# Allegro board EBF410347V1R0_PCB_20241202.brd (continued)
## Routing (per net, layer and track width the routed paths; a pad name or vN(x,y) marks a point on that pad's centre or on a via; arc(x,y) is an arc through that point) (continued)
MIPI_CSI_RX0_D2P: length 71.2
  TOP w0.114: v1(38.16,50.39) 37.84,50.07 37.27,50.07 36.94,50.4 J3.120
  ART03 w0.102: v1(38.16,50.39) 38.42,50.14 39.03,50.14 39.45,49.72 39.45,45.98 39,45.54 37.63,45.54 36.63,44.54 31.85,44.54 30.95,45.44 19.27,45.44 19.11,45.29 17.82,45.29 17.66,45.44 5.99,45.44 4.95,44.4 4.95,41.04 5.28,40.71 5.28,37.49 4.52,36.73 4.52,30.06 3.87,29.41 2.13,29.41 1.75,29.79 1.75,30.6 2.09,30.94 2.42,30.94 v1(2.78,31.3)
  BOTTOM w0.114: v1(2.78,31.3) 3.16,30.92 3.63,30.92 4.39,31.68 4.39,34.35 5.16,35.12 5.62,35.12 5.75,35.25 J28.11
MIPI_CSI_RX0_D3N: length 76
  TOP w0.114: v1(39.5,51.3) 39.17,51.63 37.27,51.63 36.94,51.3 J3.119
  ART03 w0.102: v1(1.78,34.3) 2.14,34.66 2.62,34.66 2.97,35.01 2.97,44.59 5.32,46.94 14.97,46.94 15.74,47.7 19.93,47.7 20.16,47.93 29.4,47.93 29.68,48.22 29.68,48.58 29.8,48.7 29.97,48.7 30.09,48.58 30.09,48.22 30.36,47.95 30.79,47.95 31.06,48.22 31.06,48.58 31.18,48.7 31.47,48.7 31.6,48.56 31.6,47.17 31.88,46.89 32.28,46.89 32.56,47.17 32.56,48.65 32.68,48.77 32.85,48.77 32.97,48.65 32.97,47.17 33.25,46.89 33.65,46.89 33.94,47.17 33.94,48.65 34.05,48.77 34.22,48.77 34.34,48.65 34.34,47.17 34.62,46.89 36.31,46.89 36.91,47.48 36.91,48.01 36.62,48.3 35.55,48.3 35.43,48.42 35.43,48.58 35.55,48.7 36.62,48.7 36.91,48.99 36.91,51.28 37.21,51.59 39.21,51.59 v1(39.5,51.3)
  BOTTOM w0.114: v1(1.78,34.3) 2.18,34.7 2.55,34.7 2.91,35.05 2.91,36.6 3.19,36.88 5.62,36.88 5.75,36.75 J28.8
MIPI_CSI_RX0_D3P: length 76
  TOP w0.114: J3.118 36.94,52.2 37.27,51.87 39.17,51.87 v1(39.5,52.19)
  ART03 w0.102: v1(39.5,52.19) 39.17,51.87 37.1,51.87 36.63,51.4 36.63,49.1 36.51,48.98 35.44,48.98 35.15,48.7 35.15,48.3 35.44,48.02 36.51,48.02 36.63,47.9 36.63,47.6 36.2,47.17 34.74,47.17 34.62,47.29 34.62,48.76 34.34,49.05 33.94,49.05 33.66,48.76 33.66,47.29 33.54,47.17 33.37,47.17 33.25,47.29 33.25,48.76 32.97,49.05 32.57,49.05 32.28,48.76 32.28,47.29 32.17,47.17 32,47.17 31.88,47.29 31.88,48.68 31.58,48.98 31.06,48.98 30.78,48.69 30.78,48.34 30.68,48.23 30.47,48.23 30.37,48.34 30.37,48.69 30.09,48.98 29.69,48.98 29.41,48.69 29.41,48.33 29.28,48.21 20.04,48.21 19.81,47.98 15.62,47.98 14.86,47.22 5.21,47.22 2.69,44.7 2.69,35.13 2.5,34.94 2.14,34.94 v1(1.78,35.3)
  BOTTOM w0.114: v1(1.78,35.3) 2.14,34.94 2.45,34.94 2.67,35.15 2.67,36.7 3.09,37.12 5.62,37.12 5.75,37.25 J28.7
MIPI_CSI_RX1_CLK0N: length 62.7
  TOP w0.114: J3.116 36.94,54 37.27,54.33 37.84,54.33 v1(38.16,54)
  ART03 w0.102: v1(1.78,57.97) 2.14,58.33 2.43,58.33 2.59,58.16 2.59,57.41 1.63,56.45 1.63,56.05 arc(1.59,55.95) 1.49,55.92 arc(1.4,55.88) 1.36,55.78 1.36,55.64 arc(1.4,55.55) 1.49,55.51 arc(1.59,55.47) 1.63,55.38 1.63,55.23 arc(1.59,55.14) 1.49,55.1 arc(1.4,55.06) 1.36,54.97 1.36,54.83 arc(1.4,54.74) 1.49,54.7 arc(1.59,54.66) 1.63,54.56 1.63,50.15 1.99,49.78 4.63,49.78 4.93,49.48 34.41,49.48 35.33,50.4 35.33,53.88 35.76,54.31 37.86,54.31 v1(38.16,54)
  BOTTOM w0.114: J29.10 5.75,53.15 5.62,53.27 2.36,53.27 2,53.64 2,57.86 1.89,57.97 v1(1.78,57.97)
MIPI_CSI_RX1_CLK0P: length 62.7
  TOP w0.114: v1(38.16,54.89) 37.84,54.57 37.27,54.57 36.94,54.9 J3.115
  ART03 w0.102: v1(1.78,58.97) 2.14,58.61 2.54,58.61 2.87,58.28 2.87,57.3 1.91,56.33 1.91,50.27 2.11,50.06 4.74,50.06 5.04,49.76 34.3,49.76 35.05,50.52 35.05,54 35.64,54.59 37.86,54.59 v1(38.16,54.89)
  BOTTOM w0.114: J29.9 5.75,53.65 5.62,53.52 2.46,53.52 2.24,53.74 2.24,58.16 1.78,58.63 v1(1.78,58.97)
MIPI_CSI_RX1_CLK1N: length 64.6
  TOP w0.114: J3.108 36.94,61.2 37.27,61.53 39.2,61.53 v1(39.52,61.2)
  ART03 w0.102: v1(1.78,66.78) 2.14,67.14 2.6,67.14 2.89,67.42 2.89,68.14 3.01,68.26 3.18,68.26 3.29,68.14 3.29,67.42 3.58,67.14 3.98,67.14 4.26,67.42 4.26,68.14 4.38,68.26 4.55,68.26 4.67,68.14 4.67,67.42 4.95,67.14 5.35,67.14 5.63,67.42 5.63,68.14 5.75,68.26 5.92,68.26 6.04,68.14 6.04,67.42 6.32,67.14 8.44,67.14 8.68,66.91 8.68,59.61 9.06,59.23 33.49,59.23 33.83,59.58 33.83,61.01 34.31,61.48 39.24,61.48 v1(39.52,61.2)
  BOTTOM w0.114: v1(1.78,66.78) 2.17,67.17 2.61,67.17 2.98,67.54 2.98,70.46 3.17,70.64 5.62,70.64 5.75,70.51 J30.10
MIPI_CSI_RX1_CLK1P: length 64.6
  TOP w0.114: J3.107 36.94,62.1 37.27,61.77 39.2,61.77 v1(39.52,62.09)
  ART03 w0.102: v1(1.78,67.78) 2.14,67.42 2.49,67.42 2.61,67.54 2.61,68.26 2.89,68.54 3.29,68.54 3.57,68.26 3.57,67.54 3.69,67.42 3.86,67.42 3.98,67.54 3.98,68.26 4.26,68.54 4.66,68.54 4.95,68.26 4.95,67.54 5.06,67.42 5.23,67.42 5.35,67.54 5.35,68.26 5.63,68.54 6.03,68.54 6.32,68.26 6.32,67.54 6.44,67.42 8.56,67.42 8.96,67.02 8.96,59.73 9.17,59.51 33.37,59.51 33.55,59.69 33.55,61.13 34.19,61.76 39.19,61.76 v1(39.52,62.09)
  BOTTOM w0.114: v1(1.78,67.78) 2.15,67.41 2.51,67.41 2.74,67.64 2.74,70.56 3.07,70.88 5.62,70.88 5.75,71.01 J30.9
MIPI_CSI_RX1_D0N: length 66.2
  TOP w0.114: v1(38.8,56.7) 38.8,56.88 38.65,57.03 37.27,57.03 36.94,56.7 J3.113
  ART03 w0.102: v1(38.8,56.7) 38.8,56.88 38.67,57.01 37.21,57.01 36.72,56.52 34.74,56.52 34.63,56.4 34.63,54.13 34.26,53.76 33.72,53.76 33.35,54.13 33.35,56.31 33.15,56.52 30.55,56.52 30.31,56.27 30.31,55.97 30.43,55.85 31.95,55.85 32.23,55.56 32.23,55.16 31.95,54.88 30.43,54.88 30.31,54.76 30.31,54.59 30.43,54.48 31.95,54.48 32.23,54.19 32.23,53.79 31.95,53.51 30.43,53.51 30.31,53.39 30.31,53.02 30.43,52.9 30.95,52.9 31.23,52.62 31.23,52.22 30.95,51.94 30.43,51.94 30.31,51.82 30.31,51.56 arc(30.35,51.46) 30.45,51.42 arc(30.55,51.38) 30.59,51.27 30.59,51.15 arc(30.55,51.05) 30.45,51.01 arc(30.35,50.97) 30.31,50.87 30.31,50.56 29.94,50.2 6.91,50.2 6.64,50.46 6.64,51.25 6.54,51.35 6.26,51.35 6.15,51.24 6.15,50.45 5.88,50.18 5.29,50.18 5.02,50.45 5.02,51.33 4.82,51.54 4.17,51.54 4,51.37 4,50.75 4.11,50.65 v1(4.36,50.65)
  BOTTOM w0.114: v1(4.36,50.65) 4.1,50.65 3.99,50.76 3.99,52.04 4.22,52.27 5.62,52.27 5.75,52.15 J29.12
MIPI_CSI_RX1_D0P: length 66.2
  TOP w0.114: J3.112 36.94,57.6 37.27,57.27 38.47,57.27 v1(38.8,57.59)
  ART03 w0.102: v1(3.36,50.65) 3.72,51.01 3.72,51.49 4.05,51.81 4.94,51.81 5.3,51.45 5.3,50.57 5.41,50.46 5.77,50.46 5.87,50.57 5.87,51.36 6.14,51.63 6.66,51.63 6.92,51.37 6.92,50.58 7.03,50.48 29.82,50.48 30.03,50.68 30.03,51.93 30.31,52.22 30.83,52.22 30.95,52.33 30.95,52.5 30.83,52.62 30.31,52.62 30.03,52.9 30.03,53.51 30.31,53.79 31.83,53.79 31.95,53.91 31.95,54.08 31.83,54.2 30.31,54.2 30.03,54.48 30.03,54.88 30.31,55.16 31.83,55.16 31.95,55.28 31.95,55.45 31.83,55.57 30.31,55.57 30.03,55.85 30.03,56.39 30.44,56.8 33.26,56.8 33.63,56.43 33.63,54.25 33.84,54.04 34.14,54.04 34.35,54.24 34.35,56.52 34.62,56.8 36.6,56.8 37.1,57.29 38.49,57.29 v1(38.8,57.59)
  BOTTOM w0.114: v1(3.36,50.65) 3.75,51.03 3.75,52.14 4.12,52.52 5.62,52.52 5.75,52.65 J29.11
MIPI_CSI_RX1_D1N: length 63.7
  TOP w0.114: J3.111 36.94,58.5 37.27,58.83 39.17,58.83 v1(39.5,58.5)
  ART03 w0.102: v1(39.5,58.5) 39.19,58.81 36.55,58.81 36.35,58.61 36.35,57.67 36.02,57.34 29.75,57.34 29.56,57.15 29.56,55.6 29.28,55.32 28.54,55.32 28.42,55.2 28.42,55.03 28.54,54.92 29.28,54.92 29.56,54.63 29.56,54.23 29.28,53.95 28.54,53.95 28.42,53.83 28.42,53.66 28.54,53.54 29.28,53.54 29.56,53.26 29.56,51.4 29.06,50.9 19.26,50.9 18.68,51.48 16.1,51.48 15.52,50.9 7.8,50.9 7.4,51.3 7.4,52.14 7.25,52.3 6.81,52.3 6.54,52.58 6.54,53.36 6.43,53.47 6.26,53.47 6.14,53.35 6.14,52.59 5.85,52.29 5.45,52.29 5.17,52.57 5.17,53.52 5.07,53.62 4.91,53.62 4.79,53.5 4.79,52.61 4.48,52.29 3.98,52.29 3.71,52.56 3.71,55.3 v1(3.36,55.65)
  BOTTOM w0.114: v1(3.36,55.65) 3.73,55.28 3.73,54.62 4.08,54.27 5.62,54.27 5.75,54.15 J29.8
MIPI_CSI_RX1_D1P: length 63.6
  TOP w0.114: v1(39.5,59.39) 39.17,59.07 37.27,59.07 36.94,59.4 J3.110
  ART03 w0.102: v1(4.36,55.65) 3.99,55.27 3.99,52.68 4.09,52.57 4.36,52.57 4.51,52.73 4.51,53.62 4.8,53.9 5.19,53.9 5.45,53.64 5.45,52.68 5.56,52.57 5.73,52.57 5.86,52.7 5.86,53.47 6.14,53.75 6.54,53.75 6.82,53.48 6.82,52.69 6.93,52.58 7.36,52.58 7.68,52.26 7.68,51.41 7.91,51.18 15.4,51.18 15.99,51.76 18.8,51.76 19.38,51.18 28.94,51.18 29.28,51.52 29.28,53.15 29.16,53.26 28.43,53.26 28.14,53.55 28.14,53.95 28.43,54.23 29.16,54.23 29.28,54.35 29.28,54.52 29.16,54.64 28.43,54.64 28.14,54.92 28.14,55.32 28.43,55.6 29.16,55.6 29.28,55.72 29.28,57.26 29.64,57.62 33.1,57.62 arc(33.19,57.66) 33.23,57.74 arc(33.26,57.83) 33.35,57.87 33.51,57.87 arc(33.6,57.83) 33.63,57.74 arc(33.67,57.66) 33.75,57.62 33.92,57.62 arc(34,57.66) 34.04,57.74 arc(34.07,57.83) 34.16,57.87 34.32,57.87 arc(34.41,57.83) 34.45,57.74 arc(34.48,57.66) 34.57,57.62 34.73,57.62 arc(34.82,57.66) 34.85,57.74 arc(34.89,57.83) 34.97,57.87 35.14,57.87 arc(35.22,57.83) 35.26,57.74 arc(35.29,57.66) 35.38,57.62 35.91,57.62 36.07,57.78 36.07,58.72 36.43,59.09 39.19,59.09 v1(39.5,59.39)
  BOTTOM w0.114: v1(4.36,55.65) 3.98,55.26 3.98,54.72 4.18,54.52 5.62,54.52 5.75,54.65 J29.7
MIPI_CSI_RX1_D2N: length 68.2
  TOP w0.114: v1(40.79,62.09) 41.17,61.72 41.61,61.72 41.81,61.92 41.81,62.64 41.62,62.83 38.84,62.83 38.52,63.15 38.52,63.91 38.2,64.23 37.27,64.23 36.94,63.9 J3.105
  ART03 w0.102: v1(1.78,64.78) 2.09,65.09 7.41,65.09 7.81,64.69 7.81,59.03 8.32,58.52 33.96,58.52 34.57,59.13 34.57,59.89 34.85,60.17 41.64,60.17 41.96,60.49 41.96,61.41 41.59,61.79 41.1,61.79 v1(40.79,62.09)
  BOTTOM w0.114: v1(1.78,64.78) 2.14,65.14 3.53,65.14 3.91,65.52 3.91,69.5 4.06,69.64 5.62,69.64 5.75,69.51 J30.12
MIPI_CSI_RX1_D2P: length 68.1
  TOP w0.114: v1(40.79,61.2) 41.07,61.48 41.71,61.48 42.05,61.82 42.05,62.74 41.72,63.07 38.94,63.07 38.76,63.24 38.76,64.01 38.3,64.47 37.27,64.47 36.94,64.8 J3.104
  ART03 w0.102: v1(40.79,61.2) 41.1,61.51 41.47,61.51 41.68,61.3 41.68,60.6 41.53,60.45 34.73,60.45 34.29,60.01 34.29,59.24 33.85,58.8 8.43,58.8 8.09,59.15 8.09,64.8 7.52,65.37 2.19,65.37 v1(1.78,65.78)
  BOTTOM w0.114: v1(1.78,65.78) 2.18,65.38 3.43,65.38 3.67,65.62 3.67,69.59 3.96,69.88 5.62,69.88 5.75,70.01 J30.11
MIPI_CSI_RX1_D3N: length 68.7
  TOP w0.114: v1(39.69,63.83) 40.08,64.22 40.08,65.89 39.94,66.03 37.27,66.03 36.94,65.7 J3.103
  ART03 w0.102: v1(39.69,63.83) 40.03,64.17 40.03,64.45 39.8,64.68 39.17,64.68 38.96,64.48 38.96,62.65 38.6,62.28 38.09,62.28 37.8,62.56 37.8,63.48 37.68,63.6 37.52,63.6 37.4,63.48 37.4,62.56 37.11,62.28 34.08,62.28 31.76,59.96 9.92,59.96 9.48,60.4 9.48,69.22 9.28,69.43 9.05,69.43 arc(8.94,69.38) 8.9,69.28 arc(8.86,69.18) 8.75,69.13 8.64,69.13 arc(8.54,69.18) 8.49,69.28 arc(8.45,69.38) 8.35,69.43 8.24,69.43 arc(8.13,69.38) 8.09,69.28 arc(8.05,69.18) 7.94,69.13 7.83,69.13 arc(7.73,69.18) 7.68,69.28 arc(7.64,69.38) 7.53,69.43 7.42,69.43 arc(7.32,69.38) 7.28,69.28 arc(7.23,69.18) 7.13,69.13 7.02,69.13 arc(6.91,69.18) 6.87,69.28 arc(6.83,69.38) 6.72,69.43 6.61,69.43 arc(6.51,69.38) 6.46,69.28 arc(6.42,69.18) 6.32,69.13 6.2,69.13 arc(6.1,69.18) 6.06,69.28 arc(6.01,69.38) 5.91,69.43 5.8,69.43 arc(5.69,69.38) 5.65,69.28 arc(5.61,69.18) 5.5,69.13 5.39,69.13 arc(5.29,69.18) 5.24,69.28 arc(5.2,69.38) 5.1,69.43 4.98,69.43 arc(4.88,69.38) 4.84,69.28 arc(4.79,69.18) 4.69,69.13 4.58,69.13 arc(4.47,69.18) 4.43,69.28 arc(4.39,69.38) 4.28,69.43 3.99,69.43 3.61,69.81 3.61,71.88 3.4,72.08 2.67,72.08 2.42,71.84 2.42,71.38 2.52,71.27 v1(2.78,71.27)
  BOTTOM w0.114: J30.8 5.75,71.51 5.6,71.67 2.92,71.67 2.78,71.53 v1(2.78,71.27)
MIPI_CSI_RX1_D3P: length 68.8
  TOP w0.114: J3.102 36.94,66.6 37.27,66.27 40.04,66.27 40.32,65.99 40.32,64.2 v1(40.69,63.83)
  ART03 w0.102: v1(1.78,71.27) 2.14,71.63 2.14,71.95 2.55,72.36 3.52,72.36 3.89,72 3.89,69.93 4.11,69.71 9.39,69.71 9.76,69.34 9.76,60.51 10.04,60.24 31.64,60.24 33.97,62.56 37,62.56 37.12,62.68 37.12,63.6 37.4,63.88 37.8,63.88 38.08,63.6 38.08,62.68 38.2,62.56 38.48,62.56 38.68,62.76 38.68,64.59 39.06,64.96 39.92,64.96 40.31,64.57 40.31,64.21 v1(40.69,63.83)
  BOTTOM w0.114: J30.7 5.75,72.01 5.64,71.91 2.74,71.91 2.11,71.27 v1(1.78,71.27)
MIPI_CTP_INT: length 21.6
  BOTTOM w0.173: J18.11 61.18,15.54 61.49,15.86 63.26,15.86 64.25,16.85 77.93,16.85 R176.2 R81.2
MIPI_CTP_RST: length 17.7
  BOTTOM w0.173: J18.12 60.68,15.84 61.02,16.18 63.13,16.18 64.12,17.17 73.68,17.17 R177.2 R182.2
MIPI_DSI_CLKN: length 70.2
  TOP w0.114: R106.2 v1(24.7,35.43)
  ART03 w0.102: v1(24.7,35.43) 25.06,35.79 25.06,36.05 25.37,36.36 30.18,36.36 31.37,35.17 31.37,28.98 31.65,28.7 36.87,28.7 37.13,28.44 40.54,28.44 41.57,27.41 45.25,27.41 45.75,26.91 45.75,24.97 46.18,24.54 50.71,24.54 51.18,24.07 51.18,17.02 51.38,16.81 57.86,16.81 58.17,16.51 58.17,15.1 58.41,14.86 60.6,14.86 60.92,14.55 60.92,11.97 v1(61.22,11.66)
  BOTTOM w0.114: J18.24 54.68,13.7 54.8,13.58 54.8,10.9 55.25,10.45 60.5,10.45 60.87,10.82 60.87,11.31 v1(61.22,11.66)
MIPI_DSI_CLKP: length 69.7
  TOP w0.114: R105.2 v1(25.7,35.43)
  ART03 w0.102: v1(60.33,11.66) 60.53,11.66 60.64,11.77 60.64,14.43 60.49,14.58 58.29,14.58 57.89,14.98 57.89,16.39 57.75,16.53 51.27,16.53 50.9,16.9 50.9,23.95 50.6,24.26 46.06,24.26 45.47,24.85 45.47,26.8 45.14,27.13 41.45,27.13 40.42,28.16 37.02,28.16 36.75,28.42 31.53,28.42 31.09,28.86 31.09,29.36 30.91,29.54 30.91,29.77 31.09,29.95 31.09,30.17 30.91,30.35 30.91,30.58 31.09,30.76 31.09,30.99 30.91,31.16 30.91,31.39 31.09,31.57 31.09,31.8 30.91,31.98 30.91,32.21 31.09,32.38 31.09,32.61 30.91,32.79 30.91,33.02 31.09,33.2 31.09,33.43 30.91,33.6 30.91,33.83 31.09,34.01 31.09,34.24 30.91,34.42 30.91,34.64 31.09,34.82 31.09,35.05 30.06,36.08 25.48,36.08 25.34,35.94 25.34,35.53 25.44,35.43 v1(25.7,35.43)
  BOTTOM w0.114: v1(60.33,11.66) 60.63,11.36 60.63,10.92 60.4,10.69 55.35,10.69 55.04,11 55.04,13.56 55.18,13.7 J18.23
MIPI_DSI_D0N: length 72.3
  TOP w0.114: R88.2 v1(28.7,35.43)
  ART03 w0.102: v1(28.7,35.43) 29.06,35.07 29.06,33.32 29.76,32.62 29.76,32.39 29.64,32.27 28.63,32.27 28.35,31.99 28.35,31.59 28.63,31.31 29.64,31.31 29.76,31.19 29.76,29.75 29.64,29.63 28.6,29.63 28.32,29.35 28.32,28.95 28.6,28.67 29.64,28.67 29.76,28.55 29.76,27.86 30.21,27.41 36.19,27.41 36.7,26.9 39.38,26.9 39.89,26.39 44.02,26.39 44.25,26.16 44.25,23.05 44.77,22.53 49.96,22.53 50.16,22.33 50.16,16.1 50.72,15.54 56.79,15.54 57.07,15.26 57.07,14.25 57.58,13.74 59.16,13.74 59.41,13.49 59.41,10.41 59.03,10.03 54.51,10.03 54.25,10.29 54.25,11.57 53.84,11.99 53.07,11.99 52.79,11.7 52.79,10.8 v1(52.48,10.49)
  BOTTOM w0.114: v1(52.48,10.49) 52.81,10.81 52.81,11.73 53.3,12.23 53.3,13.58 53.18,13.7 J18.27
MIPI_DSI_D0P: length 73.3
  TOP w0.114: R87.2 v1(29.7,35.43)
  ART03 w0.102: v1(53.37,10.49) 53.07,10.8 53.07,11.59 53.19,11.71 53.72,11.71 53.98,11.45 53.98,10.17 54.39,9.75 59.15,9.75 59.69,10.3 59.69,13.6 59.27,14.02 57.7,14.02 57.35,14.36 57.35,15.38 56.91,15.82 50.84,15.82 50.44,16.22 50.44,22.44 50.08,22.81 44.88,22.81 44.53,23.16 44.53,26.28 44.13,26.67 40.01,26.67 39.5,27.18 38.54,27.18 38.36,27.35 38.13,27.35 37.95,27.18 37.72,27.18 37.55,27.35 37.32,27.35 37.14,27.18 36.82,27.18 36.31,27.68 35.58,27.68 35.43,27.84 35.12,27.84 34.97,27.68 33.9,27.68 33.72,27.86 33.47,27.86 33.29,27.68 32.47,27.68 32.29,27.86 32.07,27.86 31.89,27.68 31.66,27.68 31.48,27.86 31.25,27.86 31.08,27.68 30.33,27.68 30.04,27.97 30.04,28.67 29.76,28.95 28.72,28.95 28.6,29.07 28.6,29.24 28.72,29.35 29.76,29.35 30.04,29.64 30.04,31.31 29.76,31.59 28.74,31.59 28.63,31.71 28.63,31.88 28.74,31.99 29.76,31.99 30.04,32.28 30.04,32.74 29.34,33.44 29.34,35.07 v1(29.7,35.43)
  BOTTOM w0.114: v1(53.37,10.49) 53.21,10.49 53.05,10.65 53.05,11.63 53.54,12.13 53.54,13.56 53.68,13.7 J18.26
MIPI_DSI_D1N: length 70.5
  TOP w0.114: R92.2 v1(26.7,35.43)
  ART03 w0.102: v1(26.7,35.43) 27.06,35.07 27.06,33.46 26.94,33.34 24.95,33.34 24.66,33.06 24.66,32.66 24.97,32.35 27.4,32.35 27.52,32.23 27.52,32.06 27.4,31.94 24.92,31.94 24.66,31.69 24.66,31.29 24.97,30.98 27.4,30.98 27.52,30.86 27.52,30.69 27.4,30.57 24.93,30.57 24.66,30.31 24.66,29.75 24.95,29.46 27.41,29.46 27.51,29.36 27.51,27.83 27.79,27.55 28.79,27.55 28.91,27.43 28.91,27.26 28.79,27.14 27.79,27.14 27.51,26.86 27.51,26.35 27.9,25.96 30.71,25.96 31.27,25.4 36.62,25.4 36.78,25.56 42.54,25.56 43.51,24.6 43.51,22.01 43.98,21.54 49.11,21.54 49.4,21.24 49.4,15.11 49.89,14.63 55.85,14.63 56.29,14.19 56.29,12.8 v1(55.99,12.5)
  BOTTOM w0.114: J18.21 56.18,13.7 56.31,13.57 56.31,12.82 v1(55.99,12.5)
MIPI_DSI_D1P: length 70.8
  TOP w0.114: R91.2 v1(27.7,35.43)
  ART03 w0.102: v1(27.7,35.43) 27.34,35.07 27.34,33.34 27.06,33.06 25.06,33.06 24.94,32.94 24.94,32.77 25.09,32.63 27.52,32.63 27.8,32.35 27.8,31.95 27.52,31.66 25.04,31.66 24.94,31.56 24.94,31.4 25.09,31.26 27.52,31.26 27.8,30.97 27.8,30.57 27.52,30.29 25.04,30.29 24.94,30.19 24.94,29.87 25.07,29.74 27.52,29.74 27.79,29.48 27.79,27.95 27.91,27.83 28.9,27.83 29.18,27.55 29.18,27.15 28.9,26.86 27.91,26.86 27.79,26.75 27.79,26.47 28.02,26.24 28.92,26.24 29.1,26.41 29.33,26.41 29.51,26.24 29.74,26.24 29.91,26.41 30.14,26.41 30.32,26.24 30.82,26.24 31.38,25.68 36.5,25.68 36.66,25.84 42.66,25.84 43.79,24.71 43.79,22.12 44.09,21.82 49.23,21.82 49.68,21.36 49.68,15.23 50,14.91 55.97,14.91 56.57,14.31 56.57,12.8 v1(56.88,12.5)
  BOTTOM w0.114: J18.20 56.68,13.7 56.55,13.57 56.55,12.82 v1(56.88,12.5)
MIPI_DSI_D2N: length 70.4
  TOP w0.114: R96.2 v1(22.7,35.43)
  ART03 w0.102: v1(58.7,11.45) 58.4,11.75 58.02,11.75 57.89,11.62 57.89,10.93 57.55,10.59 55.26,10.59 54.89,10.96 54.89,13.51 54.64,13.77 49.11,13.77 48.64,14.23 48.64,20.45 48.46,20.62 42.61,20.62 42.19,21.04 42.19,23.66 41.28,24.56 37,24.56 36.79,24.36 30.86,24.36 30.44,24.78 27.23,24.78 26.52,25.49 26.52,28.26 26.3,28.47 23.94,28.47 23.67,28.74 23.67,29.24 23.55,29.36 22.41,29.36 22.12,29.64 22.12,30.04 22.41,30.32 23.55,30.32 23.67,30.44 23.67,30.73 23.44,30.96 22.35,30.96 22.08,31.23 22.08,31.6 22.35,31.87 23.55,31.87 23.65,31.97 23.65,32.13 23.5,32.28 22.41,32.28 22.07,32.62 22.07,33.02 22.35,33.3 22.94,33.3 23.06,33.42 23.06,35.07 v1(22.7,35.43)
  BOTTOM w0.114: J18.18 57.68,13.7 57.81,13.57 57.81,12.08 58.12,11.77 58.38,11.77 v1(58.7,11.45)
MIPI_DSI_D2P: length 70.9
  TOP w0.114: R95.2 v1(23.7,35.43)
  ART03 w0.102: v1(58.7,12.34) 58.4,12.03 57.91,12.03 57.61,11.73 57.61,11.05 57.43,10.87 55.37,10.87 55.17,11.07 55.17,13.63 54.75,14.05 49.23,14.05 48.92,14.35 48.92,20.56 48.58,20.9 42.72,20.9 42.47,21.16 42.47,23.77 41.4,24.84 36.88,24.84 36.68,24.64 35.96,24.64 35.78,24.81 35.55,24.81 35.38,24.64 35.15,24.64 34.97,24.81 34.74,24.81 34.56,24.64 33.66,24.64 33.48,24.81 33.25,24.81 33.07,24.64 31.92,24.64 31.74,24.81 31.48,24.81 31.31,24.64 30.98,24.64 30.56,25.06 29.11,25.06 28.94,25.22 28.7,25.22 28.53,25.06 28.29,25.06 28.13,25.22 27.89,25.22 27.72,25.06 27.34,25.06 26.8,25.6 26.8,26.49 26.97,26.67 26.97,26.9 26.8,27.07 26.8,27.3 26.97,27.48 26.97,27.71 26.8,27.89 26.8,28.37 26.42,28.75 24.05,28.75 23.95,28.85 23.95,29.35 23.67,29.64 22.52,29.64 22.4,29.76 22.4,29.92 22.52,30.04 23.67,30.04 23.95,30.33 23.95,30.85 23.56,31.24 22.47,31.24 22.36,31.34 22.36,31.49 22.47,31.59 23.66,31.59 23.93,31.85 23.93,32.25 23.62,32.55 22.53,32.55 22.35,32.73 22.35,32.9 22.47,33.02 23.06,33.02 23.34,33.3 23.34,35.3 23.47,35.43 v1(23.7,35.43)
  BOTTOM w0.114: J18.17 58.18,13.7 58.05,13.57 58.05,12.18 58.22,12.01 58.38,12.01 v1(58.7,12.34)
MIPI_DSI_D3N: length 71.5
  TOP w0.114: R101.2 20.7,35.43 v1(20.7,35.43)
  ART03 w0.102: v1(20.7,35.43) 20.96,35.43 21.06,35.33 21.06,28.06 21.34,27.77 22.23,27.77 22.35,27.65 22.35,27.49 22.23,27.37 21.34,27.37 21.06,27.08 21.06,26.68 21.34,26.4 22.23,26.4 22.35,26.28 22.35,26.11 22.23,25.99 21.34,25.99 21.06,25.71 21.06,25.31 21.34,25.03 22.23,25.03 22.35,24.91 22.35,24.74 22.23,24.62 21.34,24.62 21.06,24.34 21.06,23.68 21.47,23.27 22.97,23.27 23.25,23.55 23.25,24.06 23.37,24.18 23.54,24.18 23.66,24.06 23.66,23.55 23.94,23.27 24.34,23.27 24.63,23.55 24.63,24.06 24.74,24.18 24.91,24.18 25.03,24.06 25.03,23.55 25.31,23.27 25.71,23.27 26,23.55 26,24.06 26.12,24.18 26.28,24.18 26.4,24.06 26.4,23.55 26.69,23.27 27.23,23.27 27.51,23.55 27.51,23.96 27.63,24.07 27.8,24.07 27.91,23.96 27.91,23.55 28.2,23.27 28.6,23.27 28.88,23.55 28.88,23.96 28.99,24.07 29.13,24.07 29.24,23.97 29.24,23.56 29.53,23.27 41.22,23.27 41.48,23.01 41.48,19.16 41.9,18.74 47.68,18.74 47.88,18.54 47.88,13.28 48.3,12.86 51.73,12.86 51.97,12.62 51.97,12.07 51.81,11.91 51.18,11.91 51.08,12.01 v1(51.08,12.21)
  BOTTOM w0.114: v1(51.08,12.21) 51.08,12.04 51.23,11.89 51.61,11.89 51.8,12.08 51.8,13.57 51.68,13.7 J18.30
MIPI_DSI_D3P: length 72
  TOP w0.114: R100.2 v1(21.7,35.43)
  ART03 w0.102: v1(51.08,11.32) 51.38,11.63 51.93,11.63 52.25,11.95 52.25,12.73 51.85,13.14 48.41,13.14 48.16,13.39 48.16,18.66 47.79,19.02 42.01,19.02 41.76,19.28 41.76,23.13 41.34,23.54 29.64,23.54 29.51,23.67 29.51,24.08 29.25,24.35 28.87,24.35 28.6,24.07 28.6,23.66 28.48,23.54 28.31,23.54 28.19,23.66 28.19,24.07 27.91,24.35 27.51,24.35 27.23,24.07 27.23,23.66 27.11,23.54 26.8,23.54 26.68,23.66 26.68,24.18 26.4,24.46 26,24.46 25.72,24.18 25.72,23.66 25.6,23.54 25.43,23.54 25.31,23.66 25.31,24.18 25.03,24.46 24.63,24.46 24.35,24.18 24.35,23.66 24.23,23.54 24.06,23.54 23.94,23.66 23.94,24.18 23.66,24.46 23.26,24.46 22.97,24.18 22.97,23.66 22.86,23.54 21.59,23.54 21.34,23.79 21.34,24.22 21.46,24.34 22.35,24.34 22.63,24.63 22.63,25.03 22.35,25.31 21.46,25.31 21.34,25.43 21.34,25.6 21.46,25.72 22.35,25.72 22.63,26 22.63,26.4 22.35,26.68 21.46,26.68 21.34,26.8 21.34,26.97 21.46,27.09 22.35,27.09 22.63,27.37 22.63,27.77 22.35,28.05 21.46,28.05 21.34,28.17 21.34,35.07 v1(21.7,35.43)
  BOTTOM w0.114: v1(51.08,11.32) 51.4,11.64 51.71,11.64 52.04,11.98 52.04,13.57 52.18,13.7 J18.29
MIPI_DSI_TX_CLKN: length 25.2
  TOP w0.114: J3.135 36.94,36.9 37.27,37.23 39.14,37.23 39.38,36.98 39.38,36.59 39.27,36.47 v1(39.06,36.47) ; R107.1 v1(24.7,33.72) R106.1
  BOTTOM w0.114: v1(39.06,36.47) 39.38,36.15 39.38,35.99 39.24,35.84 38.85,35.84 38.44,36.24 38.44,36.69 37.68,37.45 33.78,37.45 32.96,36.62 32.96,34.43 32.69,34.17 30.73,34.17 30.21,34.68 25.4,34.68 25.08,34.36 25.08,34.1 v1(24.7,33.72)
MIPI_DSI_TX_CLKP: length 25.6
  TOP w0.114: R105.1 v1(25.7,33.72) R104.1 ; v1(39.95,36.47) 39.74,36.47 39.62,36.59 39.62,37.08 39.24,37.47 37.27,37.47 36.94,37.8 J3.134
  BOTTOM w0.114: v1(39.95,36.47) 39.62,36.15 39.62,35.89 39.34,35.6 38.75,35.6 38.2,36.14 38.2,36.59 37.58,37.21 33.88,37.21 33.2,36.52 33.2,34.33 32.79,33.92 30.63,33.92 30.11,34.44 25.5,34.44 25.32,34.26 25.32,34.1 v1(25.7,33.72)
MIPI_DSI_TX_D0N: length 23.1
  TOP w0.114: R89.1 v1(28.7,33.72) R88.1 ; J3.138 36.94,34.2 37.27,34.53 39.17,34.53 v1(39.5,34.2)
  BOTTOM w0.114: v1(28.7,33.72) 28.99,33.72 29.48,33.22 33.67,33.22 33.92,33.48 33.92,36.21 34.18,36.46 35.86,36.46 35.98,36.35 35.98,35.05 36.23,34.8 36.78,34.8 37.03,35.05 37.03,36.18 37.15,36.3 37.31,36.3 37.45,36.16 37.45,34.98 37.91,34.53 39.17,34.53 v1(39.5,34.2)
MIPI_DSI_TX_D0P: length 22.1
  TOP w0.114: v1(39.5,35.09) 39.17,34.77 37.27,34.77 36.94,35.1 J3.137 ; R87.1 v1(29.7,33.72) R86.1
  BOTTOM w0.114: v1(39.5,35.09) 39.17,34.77 38.01,34.77 37.69,35.08 37.69,36.26 37.41,36.54 37.05,36.54 36.79,36.28 36.79,35.15 36.68,35.04 36.33,35.04 36.22,35.15 36.22,36.45 35.96,36.7 34.08,36.7 33.68,36.31 33.68,33.58 33.57,33.47 29.82,33.47 29.7,33.58 v1(29.7,33.72)
MIPI_DSI_TX_D1N: length 24.9
  TOP w0.114: R93.1 v1(26.7,33.72) R92.1 ; J3.140 36.94,32.4 37.27,32.73 37.84,32.73 v1(38.16,32.4)
  BOTTOM w0.114: v1(26.7,33.72) 27.08,33.34 27.08,32.77 27.34,32.51 34.38,32.51 34.63,32.77 34.63,35.58 34.77,35.72 35.15,35.72 35.27,35.61 35.27,32.33 35.68,31.93 36.2,31.93 36.53,32.26 36.53,33.71 36.64,33.82 37.01,33.82 37.12,33.71 37.12,33.02 37.42,32.73 37.84,32.73 v1(38.16,32.4)
MIPI_DSI_TX_D1P: length 24.5
  TOP w0.114: R91.1 v1(27.7,33.72) R90.1 ; v1(38.16,33.29) 37.84,32.97 37.27,32.97 36.94,33.3 J3.139
  BOTTOM w0.114: v1(38.16,33.29) 37.84,32.97 37.52,32.97 37.36,33.12 37.36,33.81 37.11,34.06 36.54,34.06 36.29,33.81 36.29,32.36 36.1,32.17 35.78,32.17 35.51,32.43 35.51,35.71 35.25,35.97 34.67,35.97 34.39,35.68 34.39,32.87 34.28,32.75 27.44,32.75 27.32,32.87 27.32,33.34 v1(27.7,33.72)
MIPI_DSI_TX_D2N: length 24.9
  TOP w0.114: R97.1 v1(22.7,33.72) R96.1 ; v1(39.5,30.6) 39.17,30.93 37.27,30.93 36.94,30.6 J3.142
  BOTTOM w0.114: v1(39.5,30.6) 39.17,30.93 34.64,30.93 33.78,31.79 24.98,31.79 24.71,32.06 24.71,32.47 24.57,32.6 24.38,32.6 24.25,32.47 24.25,32.06 23.97,31.79 23.34,31.79 23.08,32.04 23.08,33.34 v1(22.7,33.72)
MIPI_DSI_TX_D2P: length 24.5
  TOP w0.114: R94.1 v1(23.7,33.72) R95.1 ; v1(39.5,31.49) 39.17,31.17 37.27,31.17 36.94,31.5 J3.141
  BOTTOM w0.114: v1(23.7,33.72) 23.32,33.34 23.32,32.14 23.44,32.03 23.87,32.03 24.01,32.16 24.01,32.57 24.28,32.84 24.67,32.84 24.95,32.57 24.95,32.16 25.08,32.03 33.88,32.03 34.74,31.17 39.17,31.17 v1(39.5,31.49)
MIPI_DSI_TX_D3N: length 23.8
  TOP w0.114: J3.144 36.94,28.8 37.27,29.13 37.84,29.13 v1(38.16,28.8) ; R101.1 20.7,33.72 v1(20.7,33.72) R102.1
  BOTTOM w0.114: v1(20.7,33.72) 21.08,33.34 21.08,32.02 22.04,31.06 33.45,31.06 35.39,29.13 37.84,29.13 v1(38.16,28.8)
MIPI_DSI_TX_D3P: length 23.4
  TOP w0.114: R100.1 v1(21.7,33.72) 21.7,33.72 R99.1 ; v1(38.16,29.69) 37.84,29.37 37.27,29.37 36.94,29.7 J3.143
  BOTTOM w0.114: v1(21.7,33.72) 21.32,33.34 21.32,32.12 22.14,31.3 33.55,31.3 35.49,29.37 37.84,29.37 v1(38.16,29.69)
MIPI_LCD_PWR_EN: length 106
  TOP w0.173: J3.25 85.35,45 v1(85.45,44.9)
  ART03 w0.16: v1(41.63,41.27) 40.22,41.27 39.9,40.95 39.9,38.78 38.63,37.51 32.27,37.51 31.95,37.83 31.95,39.94 31.63,40.26 23.18,40.26 22.86,39.94 22.86,37.4 22.54,37.08 15.75,37.08 14.73,36.07 11.58,36.07 10.92,35.41 10.92,31.39 10.57,31.04 10.01,31.04 9.7,30.73 9.7,21.99 v1(10.36,21.33)
  BOTTOM w0.173: v1(85.45,44.9) 85.45,40.5 85.1,40.16 49.68,40.16 48.57,41.27 v1(41.63,41.27) ; R179.1 10.36,21.4 v1(10.36,21.33)
MIPI_LCD_RST: length 11.3
  BOTTOM w0.173: J18.15 59.18,16.53 59.49,16.84 62.87,16.84 63.93,17.91 67.17,17.91 R186.2
ON/OFF_KEY: length 98.4
  TOP w0.173: v1(85.46,32.2) 85.26,32.4 J3.11
  ART03 w0.16: v1(119.91,45.3) 119.43,44.83 114.29,44.83 113.97,44.51 113.97,35.2 113.56,34.8 95.74,34.8 95.41,34.47 95.41,32.82 95.02,32.43 91.77,32.43 91.39,32.81 v1(91.39,33.55) 91.38,33.55 90.82,34.11 87.47,34.11 87.15,33.79 87.15,32.52 86.83,32.2 v1(85.46,32.2)
  BOTTOM w0.173: v1(119.91,45.3) 120.75,46.15 120.75,50.21 120.4,50.57 120.4,56.41 118.72,58.08 103.23,58.08 102.92,58.39 102.92,67.08 103.41,67.57 109.54,67.57 110.06,67.05 D46.2 ; R71.2 v1(91.39,33.55)
PCM_CLK: length 6.6
  TOP w0.173: U16.26 106.86,53.84 108.07,52.64 108.07,50.07 R160.1
PCM_DIN: length 3.6
  TOP w0.173: U16.27 107.76,53.93 108.79,52.91 R159.1
PCM_OUT: length 3.9
  TOP w0.173: R161.1 105.96,53.74 U16.25
PCM_SYNC: length 6.4
  TOP w0.173: U16.28 108.66,53.95 109.4,53.21 109.4,50.13 R157.1
PWM3_IR: length 20.4
  TOP w0.173: v1(73.41,10.95) 74.27,10.08 81.09,10.08 81.44,10.43 81.44,19.88 81.19,20.13 J3.199
  BOTTOM w0.173: R108.1 v1(73.41,10.95)
RECOVERY/ADC_KEY: length 77.2
  TOP w0.173: v1(85.59,53.72) 85.31,54 J3.35
  ART03 w0.16: v1(96.61,31.84) 96.61,33.61 97.11,34.11 113.3,34.11 v1(113.7,33.7)
  BOTTOM w0.173: v1(96.61,31.84) D34.1 94.75,30.89 93.91,30.89 93.66,30.64 J16.3 ; v1(85.59,53.72) 86.1,53.21 95.48,53.21 96.19,52.5 99.26,52.5 99.93,51.83 105.76,51.83 106.78,52.85 109.35,52.85 110.23,51.97 115.32,51.97 116,51.3 116,50.87 116,48.88 115.01,47.89 115.01,41.61 113.7,40.3 v1(113.7,33.7)
RESET_KEY: length 13.1
  TOP w0.173: J3.12 85.36,33.3 v1(85.46,33.2)
  ART03 w0.203: v1(85.46,33.2) 86.13,33.2 86.44,33.5 86.44,34.4 86.76,34.72 93.99,34.72 94.31,34.4 v1(94.31,33.53)
  BOTTOM w0.173: R72.2 v1(94.31,33.53)
RS232_1_3V3: length 35.4
  TOP w0.381: J32.1 89.66,20.8 90.42,20.04 92.02,20.04 92.66,19.41 J34.1 ; U23.16 90.58,39.83 90.24,39.49 C144.1 88.36,39.49 L14.1 v1(88.06,40.66)
  BOTTOM w0.381: v1(88.06,40.66) 87.05,40.66 86.41,40.03 86.41,30.48 86.79,30.1 87.96,30.1 88.34,29.72 88.34,23.16 J32.1
RS232_1_R1IN: length 45.9
  TOP w0.254: J34.3 88.66,18.55 87.73,19.48 87.73,31.98 88.36,32.61 v1(88.74,32.61) ; R116.2 v1(90.45,46.68) ; U23.13 v1(94.38,40.26)
  ART03 w0.254: v1(90.45,46.68) 90.45,39.6 90.85,39.19 93.98,39.19 94.38,39.6 v1(94.38,40.26)
  BOTTOM w0.254: v1(88.74,32.61) 88.17,32.61 87.91,32.86 87.91,35.2 88.22,35.51 93.96,35.51 94.38,35.93 v1(94.38,40.26)
RS232_1_R2IN: length 30.3
  TOP w0.254: v1(99.46,37.67) U23.8 99.46,32.28 97.54,30.35 97.54,24.99 96.95,24.41 93.93,24.41 93.66,24.13 J32.3 ; R113.2 v1(98.19,46.68)
  ART03 w0.254: v1(99.46,37.67) 98.91,38.22 98.91,45.97 v1(98.19,46.68)
RS232_1_T1OUT: length 41.6
  TOP w0.254: U23.14 v1(93.12,40.26) ; R118.2 v1(92.99,46.68) ; v1(88.74,31.61) 88.47,31.34 88.47,19.94 89.13,19.28 90.2,19.28 90.66,18.81 J34.2
  ART03 w0.254: v1(92.99,46.68) 92.18,45.88 92.18,41.21 v1(93.12,40.26)
  BOTTOM w0.254: v1(93.12,40.26) 93.12,36.66 92.79,36.32 87.84,36.32 87.2,35.69 87.2,31.98 87.57,31.61 v1(88.74,31.61)
RS232_1_T2OUT: length 33
  TOP w0.254: v1(98.2,37.67) U23.7 98.2,35.05 98.55,34.7 98.55,32.41 96.78,30.63 96.78,25.7 96.29,25.22 92.18,25.22 91.66,24.7 J32.2 ; R114.2 v1(95.55,46.68)
  ART03 w0.254: v1(98.2,37.67) 96.68,37.67 96.27,38.07 96.27,45.97 v1(95.55,46.68)
RS232_2_3V3: length 34.2
  TOP w0.381: U25.16 104.22,39.96 103.75,39.49 C150.1 101.54,39.49 L16.1 99.58,39.79 v1(99.46,39.67) ; J37.1 104.91,20.08 104.47,20.52 101.49,20.52 J35.1
  BOTTOM w0.381: J35.1 100.13,21.88 100.13,39 v1(99.46,39.67)
RS232_2_R1IN: length 55.8
  TOP w0.254: R126.2 v1(104.24,46.68) ; v1(101.44,32.56) 100.82,32.56 98.3,30.05 98.3,19.84 99.16,18.97 100.41,18.97 100.91,18.47 J37.3 ; U25.13 v1(108.02,40.26)
  ART03 w0.254: v1(108.02,40.26) 108.02,44.61 107.55,45.08 104.68,45.08 104.24,45.52 v1(104.24,46.68)
  BOTTOM w0.254: v1(101.44,32.56) 101.44,39.15 101.79,39.5 107.26,39.5 v1(108.02,40.26) 108.05,40.29 108.05,44.96 107.49,45.52 107.49,46.84 106.96,47.37 104.9,47.37 104.24,46.71 v1(104.24,46.68)
RS232_2_R2IN: length 40.7
  TOP w0.254: J35.3 104.17,24.72 103.56,25.32 101.35,25.32 100.82,25.86 100.82,29.11 101.55,29.84 112.44,29.84 113.1,30.51 U25.8 v1(113.1,37.67) ; R123.2 v1(111.86,46.68)
  ART03 w0.254: v1(111.86,46.68) 112.6,46.68 113.1,46.18 v1(113.1,37.67)
RS232_2_T1OUT: length 44
  TOP w0.254: U25.14 v1(106.76,40.26) ; R128.2 v1(106.78,46.68) ; J37.2 102.91,19.39 102.54,19.76 99.47,19.76 98.99,20.24 98.99,29.64 100.91,31.56 v1(101.44,31.56)
  BOTTOM w0.254: v1(106.78,46.68) 106.78,45.49 107.65,44.63 107.65,41.14 v1(106.76,40.26) 101.2,40.26 100.86,39.93 100.86,32.14 v1(101.44,31.56)
RS232_2_T2OUT: length 39.8
  TOP w0.254: v1(111.84,37.67) U25.7 111.84,35.07 112.3,34.62 112.3,31.01 111.92,30.63 101.15,30.63 100,29.49 100,24.87 100.51,24.36 101.58,24.36 102.17,23.77 J35.2 ; R124.2 v1(109.32,46.68)
  ART03 w0.254: v1(111.84,37.67) 111.35,38.16 111.35,43 110.06,44.29 110.06,45.95 v1(109.32,46.68)
RS485_1_3V3: length 30.2
  TOP w0.381: J33.1 v1(117.17,14.22)
  BOTTOM w0.381: U24.8 106.1,11.17 105.8,10.88 C153.1 L15.2 104.31,16.65 D54.2 105.06,17.63 116.59,17.63 117.17,17.04 117.17,14.23 v1(117.17,14.22)
RS485_1_A: length 24.2
  TOP w0.254: v1(98.12,12.57) 98.31,12.57 98.99,11.89 106.25,11.89 106.53,12.17 106.53,13.18 v1(105.99,13.71) ; J33.3 v1(113.17,14.22)
  BOTTOM w0.254: v1(105.99,13.71) U24.6 109.47,13.71 R110.2 ; R115.2 v1(98.12,12.57) ; R110.2 109.9,13.28 113.77,13.28 114.02,13.54 114.02,13.97 113.77,14.22 v1(113.17,14.22) ; R110.2 R109.1
RS485_1_B: length 27.5
  TOP w0.254: v1(97.1,16.76) 97.74,16.13 97.74,13.71 99.16,12.29 105.84,12.29 v1(105.99,12.44) ; J33.2 v1(115.17,14.22)
  BOTTOM w0.254: R117.2 v1(97.1,16.76) ; R110.1 109.61,12.58 109.91,12.88 113.93,12.88 114.43,13.37 114.43,14.04 114.61,14.22 v1(115.17,14.22) ; R110.1 R112.1 ; R110.1 109.47,12.44 U24.7 v1(105.99,12.44)
RS485_1_DIR: length 91.9
  TOP w0.173: J3.62 72.19,68.12 71.83,67.77 71.07,67.77 70.57,67.27 v1(70.35,67.27)
  ART03 w0.16: v1(70.35,67.27) 70.99,66.63 70.99,20.26 71.31,19.94 82.83,19.94 83.19,19.58 83.19,18.73 83.51,18.41 97.41,18.41 97.73,18.09 97.73,15.31 97.18,14.76 v1(97.1,14.76)
  BOTTOM w0.173: v1(97.1,14.76) 97.39,14.48 99.48,14.48 R111.1
  BOTTOM w0.254: R111.1 100.24,13.71 U24.3 103.48,13.71 103.68,13.51 103.68,12.65 103.48,12.44 U24.2
RS485_2_3V3: length 36.5
  BOTTOM w0.381: J36.1 109.3,20.47 90.47,20.47 89.74,19.74 D66.2 89.74,9.69 L17.2 C156.1 91.19,10.93 91.44,11.17 U26.8
RS485_2_A: length 54.3
  TOP w0.254: v1(83.69,12.57) 90.39,12.57 91.05,11.91 91.77,11.91 92.02,12.17 92.02,13.18 v1(91.49,13.71)
  BOTTOM w0.173: R120.2 95.03,13.58
  BOTTOM w0.254: v1(91.49,13.71) U26.6 94.89,13.71 R120.2 R119.1 ; R125.2 v1(83.69,12.57) ; J36.3 113.82,22.7 113.82,23.49 114.25,23.93 117.37,23.93 117.63,23.67 117.63,20.14 117.12,19.63 96.63,19.63 95.94,18.94 95.94,13.44 95.78,13.28 95.33,13.28 95.03,13.58
RS485_2_B: length 57.4
  TOP w0.254: v1(83.69,16.76) 83.77,16.69 83.77,13.41 84.2,12.98 90.58,12.98 91.11,12.44 v1(91.49,12.44)
  BOTTOM w0.254: R120.1 R122.1 ; R120.1 94.89,12.44 U26.7 v1(91.49,12.44) ; R120.1 95.32,12.88 95.96,12.88 96.34,13.26 96.34,18.77 96.8,19.23 117.36,19.23 118.03,19.9 118.03,23.92 117.62,24.33 114.08,24.33 113.41,23.66 113.41,22.58 J36.2 ; R127.2 v1(83.69,16.76)
RS485_2_DIR: length 79.3
  TOP w0.173: v1(71.35,67.27) 72.74,67.27 73.09,67.61 J3.61
  ART03 w0.16: v1(83.82,19.42) 83.82,20.01 83.39,20.45 71.82,20.45 71.5,20.77 71.5,67.12 v1(71.35,67.27)
  BOTTOM w0.173: v1(83.82,19.42) 83.82,18.06 83.62,17.86 82.75,17.86 82.04,17.14 82.04,14.9 82.37,14.58 85.05,14.58 R121.1
  BOTTOM w0.254: R121.1 85.92,13.71 U26.3 89,13.71 89.2,13.51 89.2,12.65 89,12.44 U26.2
RTC_INT: length 71.7
  TOP w0.173: J3.197 79.39,23.35 79.73,23.7 81.11,23.7 81.46,24.04 81.46,58.03 v1(82.04,58.61)
  ART03 w0.16: v1(82.04,58.61) 82.04,61.46 82.4,61.82 90.65,61.82 90.98,61.49 93.34,61.49 94.97,63.12 98.15,63.12 98.65,63.63 98.65,64.24 99.03,64.62 99.03,65.25 99.49,65.71 v1(103.96,65.71)
  BOTTOM w0.173: D45.2 104.1,65.84 v1(103.96,65.71)
SARADC0_BOOT: length 71.3
  TOP w0.173: v1(34.44,42.49) 34.44,48.61 34.04,49.01 R261.1 ; J3.36 v1(82.8,54.9)
  BOTTOM w0.173: v1(82.8,54.9) 81.24,54.9 81.16,54.83 50.79,54.83 50.46,54.5 50.46,43.5 50.11,43.15 38.99,43.15 38.25,43.89 34.79,43.89 34.44,43.54 v1(34.44,42.49)
SARADC0_IN3: length 4.1
  TOP w0.173: v1(82.8,53.9) 82.8,53.34 83.04,53.1 J3.34
  BOTTOM w0.173: R171.2 R173.1 83.14,53.9 v1(82.8,53.9)
SARADC0_IN5: length 54.2
  TOP w0.173: J3.32 86.79,51.3 v1(88.2,49.9)
  BOTTOM w0.173: R145.2 102.44,37.06 102.9,37.51 108.72,37.51 108.89,37.69 108.89,42.26 109.38,42.75 111.64,42.75 112.42,43.53 112.42,48.9 112.08,49.24 88.85,49.24 v1(88.2,49.9)
SARADC0_IN6: length 54.3
  TOP w0.173: J3.31 85.46,50.4 v1(85.95,49.91)
  BOTTOM w0.173: v1(85.95,49.91) 86.47,49.39 87.35,49.39 87.53,49.57 87.53,50.22 87.7,50.39 88.62,50.39 89.25,49.76 112.6,49.76 112.94,49.42 112.94,42.77 112.36,42.19 109.91,42.19 109.45,41.73 109.45,37.17 109.28,37 105.07,37 104.72,36.65 104.72,32.86 R146.2
SARADC0_IN7: length 53.9
  TOP w0.173: v1(86.95,49.91) 86.35,49.3 85.6,49.3 85.4,49.5 J3.30
  BOTTOM w0.173: v1(86.95,49.91) 86.95,50.42 87.44,50.92 88.91,50.92 89.55,50.28 106.59,50.28 107.59,51.28 108.64,51.28 109.64,50.28 112.81,50.28 113.46,49.63 113.46,49.2 113.46,42.49 112.47,41.5 111,41.5 110.64,41.15 110.64,36.65 110.47,36.47 107.36,36.47 107.01,36.13 R147.2
SARADC1_IN0: length 58.9
  TOP w0.173: J3.83 53.29,67.8 v1(53.86,67.22)
  ART03 w0.16: v1(53.86,67.22) 54.4,66.68 56.43,66.68 56.76,66.35 56.76,21.27 57.08,20.95 60.61,20.95 v1(62.15,19.41)
  BOTTOM w0.173: R139.2 61.96,20.44 62.15,20.25 v1(62.15,19.41)
SARADC1_IN1: length 57.9
  TOP w0.173: v1(53.86,68.27) 54.19,68.6 J3.82
  ART03 w0.16: v1(60.15,19.41) 59.09,20.47 56.6,20.47 56.28,20.79 56.28,65.34 55.96,65.66 53.66,65.66 53.34,65.98 53.34,67.75 v1(53.86,68.27)
  BOTTOM w0.173: v1(60.15,19.41) 60.15,20.21 59.92,20.44 R140.2
SARADC1_IN2: length 59.1
  TOP w0.173: v1(54.86,68.27) 55.09,68.5 J3.81
  ART03 w0.16: v1(54.86,68.27) 54.35,68.78 53.14,68.78 52.83,68.48 52.83,65.47 53.15,65.15 55.41,65.15 55.73,64.83 55.73,20.28 56.05,19.96 57.6,19.96 v1(58.15,19.41)
  BOTTOM w0.173: v1(58.15,19.41) 58.15,20.28 57.99,20.44 R141.2
SARADC1_IN3: length 60.5
  TOP w0.173: J3.80 55.99,68.4 v1(55.86,68.27)
  ART03 w0.16: v1(55.86,68.27) 55.86,68.98 55.54,69.3 52.67,69.3 52.35,68.98 52.35,64.98 52.67,64.66 54.92,64.66 55.24,64.34 55.24,19.73 55.57,19.41 v1(56.15,19.41)
  BOTTOM w0.173: R142.2 55.93,20.44 56.15,20.22 v1(56.15,19.41)
SARADC1_IN4: length 66.5
  TOP w0.173: J3.79 56.89,68.04 56.62,67.77 55.41,67.77 v1(54.86,67.22)
  ART03 w0.16: v1(54.86,67.22) 55.35,67.72 56.04,67.72 56.36,68.04 56.36,69.47 56.06,69.78 52.19,69.78 51.87,69.46 51.87,64.45 52.19,64.13 54.42,64.13 54.74,63.81 54.74,20 v1(54.15,19.41)
  BOTTOM w0.173: v1(54.15,19.41) 54.15,20.21 53.92,20.44 R143.2
SARADC1_IN5: length 69.4
  TOP w0.173: J3.78 57.79,67.57 57.44,67.22 v1(55.86,67.22)
  ART03 w0.16: v1(52.15,19.41) 53.25,19.41 54.23,20.4 54.23,63.31 53.91,63.63 51.71,63.63 51.39,63.95 51.39,69.94 51.71,70.26 56.29,70.26 56.84,69.7 56.84,67.48 56.58,67.22 v1(55.86,67.22)
  BOTTOM w0.173: R144.2 51.84,20.44 52.15,20.13 v1(52.15,19.41)
SARADC1_IN6: length 97.5
  TOP w0.173: J3.77 58.69,65.72 59.14,65.27 v1(66.35,65.27)
  ART03 w0.16: v1(66.01,50.62) 65.95,50.68 65.95,64.86 v1(66.35,65.27)
  BOTTOM w0.173: R148.2 109.3,35.52 109.64,35.86 110.87,35.86 111.2,36.19 111.2,40.54 111.63,40.97 112.7,40.97 113.98,42.25 113.98,48.47 114.6,49.1 114.6,49.96 114.18,50.39 113.54,50.39 113.11,50.82 109.86,50.82 108.86,51.81 107.39,51.81 106.38,50.8 89.82,50.8 89.18,51.43 86.28,51.43 85.47,50.62 v1(66.01,50.62)
SARADC1_IN7: length 96
  TOP w0.173: J3.76 59.59,66.61 59.93,66.27 v1(65.35,66.27)
  ART03 w0.16: v1(65.35,66.27) 64.99,65.9 64.99,51.16 v1(64.97,51.14)
  BOTTOM w0.173: R149.2 111.58,35.84 112.42,36.68 112.42,39.88 114.5,41.95 114.5,48.2 115.48,49.18 115.48,51.08 115.11,51.45 110.01,51.45 109.13,52.33 107.02,52.33 106.01,51.32 90.03,51.32 89.39,51.95 86.01,51.95 85.2,51.14 v1(64.97,51.14)
SDMMC0_CLK: length 69.8
  TOP w0.173: J3.179 63.19,24.28 62.84,24.63 v1(61.39,24.63)
  ART03 w0.16: v1(61.39,24.63) 59.76,26.25 59.76,70.69 59.95,70.87 64.31,70.87 64.57,71.13 64.57,76.69 64.31,76.94 60.5,76.94 60.3,77.15 60.3,77.45 60.49,77.64 61.44,77.64 61.66,77.86 v1(61.66,78.55)
  BOTTOM w0.173: R46.1 v1(61.66,78.55)
SDMMC0_CMD: length 69.9
  TOP w0.173: J3.178 62.29,23.28 61.94,23.63 v1(61.39,23.63)
  ART03 w0.16: v1(61.39,23.63) 59.28,25.73 59.28,71.18 59.62,71.51 62.97,71.51 63.38,71.92 63.38,76.18 63.09,76.46 59.77,76.46 59.59,76.65 59.59,77.47 59.43,77.63 59.11,77.63 58.95,77.47 58.95,76.65 58.76,76.46 58.47,76.46 58.23,76.7 v1(58.23,78.55)
  BOTTOM w0.173: R45.1 v1(58.23,78.55)
SDMMC0_D0: length 69.6
  TOP w0.173: v1(58.79,22.63) 58.69,22.53 J3.174
  ART03 w0.16: v1(58.79,22.63) 57.36,24.05 57.36,70.43 54.87,72.93 54.87,77.54 54.43,77.98 54.43,78.69 55.61,79.87 62.05,79.87 62.8,79.11 v1(62.8,78.55)
  BOTTOM w0.173: R47.1 v1(62.8,78.55)
SDMMC0_D1: length 70.6
  TOP w0.173: J3.175 59.59,22.43 v1(59.79,22.63)
  ART03 w0.16: v1(59.79,22.63) 57.84,24.57 57.84,70.79 55.46,73.17 55.46,78.96 55.88,79.38 61.81,79.38 62.2,78.99 62.2,78.1 62.52,77.78 63.63,77.78 63.95,78.1 v1(63.95,78.55)
  BOTTOM w0.173: R48.1 v1(63.95,78.55)
SDMMC0_D2: length 69.7
  TOP w0.173: J3.176 60.49,23.28 60.14,23.63 v1(59.79,23.63)
  ART03 w0.16: v1(55.95,78.55) 56.25,78.55 56.49,78.31 56.49,73.83 56.68,73.64 56.94,73.64 57.13,73.83 57.13,74.57 57.32,74.76 57.56,74.76 57.74,74.57 57.74,73.83 57.9,73.67 58.13,73.67 58.29,73.83 58.29,74.55 58.48,74.74 58.77,74.74 58.95,74.55 58.95,73.83 59.14,73.64 59.37,73.64 59.53,73.8 59.53,74.55 59.69,74.71 60,74.71 60.16,74.55 60.16,72.74 59.89,72.47 59.25,72.47 58.86,72.47 58.32,71.94 58.32,25.09 v1(59.79,23.63)
  BOTTOM w0.173: R43.1 v1(55.95,78.55)
SDMMC0_D3: length 69.7
  TOP w0.173: J3.177 v1(61.39,22.63)
  ART03 w0.16: v1(57.09,78.55) 57.58,78.05 57.58,75.62 57.91,75.29 60.64,75.29 60.83,75.11 60.83,73.86 61.02,73.67 61.28,73.67 61.47,73.86 61.47,75.11 61.66,75.29 62.15,75.29 62.38,75.07 62.38,72.32 62.05,71.99 59.05,71.99 58.8,71.74 58.8,25.45 61.39,22.86 v1(61.39,22.63)
  BOTTOM w0.173: R44.1 v1(57.09,78.55)
SDMMC0_DETN: length 70.4
  TOP w0.173: v1(61.39,25.63) 63.74,25.63 64.09,25.28 J3.180
  ART03 w0.16: v1(65.09,78.55) 64.65,78.55 64.49,78.71 64.49,79.56 64.74,79.82 65.75,79.82 65.94,79.63 65.94,70.77 65.56,70.39 60.48,70.39 60.24,70.16 60.24,26.77 v1(61.39,25.63)
  BOTTOM w0.173: R49.1 v1(65.09,78.55)
SDMMC1_CLK: length 99.6
  TOP w0.173: J3.172 56.89,29.3 57.23,29.64 74.53,29.64 75.01,30.11 75.01,50.65 75.34,50.98 76.49,50.98 v1(77.17,51.65) ; v1(103.97,61.71) 103.67,61.41 U16.17
  ART03 w0.16: v1(103.97,61.71) 103.24,61.71 102.77,61.24 102.77,53.21 102.44,52.88 101.48,52.88 101.29,52.69 101.29,51.82 101.1,51.64 100.84,51.64 100.65,51.82 100.65,52.69 100.46,52.88 100.2,52.88 100.01,52.69 100.01,51.82 99.82,51.64 99.56,51.64 99.37,51.82 99.37,52.69 99.18,52.88 98.55,52.88 98.37,52.69 98.37,51.8 98.18,51.61 97.91,51.61 97.73,51.8 97.73,52.69 97.54,52.88 97.27,52.88 97.09,52.69 97.09,51.8 96.9,51.61 96.63,51.61 96.45,51.8 96.45,52.69 96.26,52.88 94.56,52.88 94.37,52.69 94.37,51.8 94.18,51.61 93.92,51.61 93.73,51.8 93.73,52.69 93.54,52.88 93.28,52.88 93.09,52.69 93.09,51.8 92.9,51.61 92.64,51.61 92.45,51.8 92.45,52.69 92.26,52.88 91.88,52.88 91.72,52.72 91.72,51.84 91.53,51.65 v1(77.17,51.65)
SDMMC1_CMD: length 100
  TOP w0.173: v1(76.17,51.65) 76.07,51.56 74.86,51.56 74.49,51.19 74.49,30.67 74.02,30.2 56.33,30.2 55.99,29.85 J3.171 ; U16.16 103.57,62.3 v1(103.97,62.71)
  ART03 w0.16: v1(103.97,62.71) 102.94,62.71 102.29,62.06 102.29,53.75 101.98,53.44 101.69,53.44 101.53,53.6 101.53,54.85 101.34,55.04 101.08,55.04 100.89,54.85 100.89,53.65 100.68,53.44 100.41,53.44 100.25,53.6 100.25,54.85 100.06,55.04 99.8,55.04 99.61,54.85 99.61,53.65 99.4,53.44 98.05,53.44 97.86,53.63 97.86,54.88 97.67,55.07 97.41,55.07 97.22,54.88 97.22,53.63 97.03,53.44 96.77,53.44 96.58,53.63 96.58,54.88 96.39,55.07 96.13,55.07 95.94,54.88 95.94,53.63 95.75,53.44 91.49,53.44 91.14,53.08 91.14,52.4 90.88,52.14 76.65,52.14 v1(76.17,51.65)
SDMMC1_D0: length 99
  TOP w0.173: J3.167 52.39,31.94 52.73,32.28 71.82,32.28 72.29,32.75 72.29,53.46 72.63,53.81 v1(76.17,53.81) ; U16.18 103.77,60.51 v1(103.97,60.71)
  ART03 w0.16: v1(76.17,53.81) 75.49,53.13 75.49,51.43 75.79,51.13 101.8,51.13 101.96,51.29 101.96,52.06 102.15,52.25 102.41,52.25 102.6,52.06 102.6,51.29 102.76,51.13 103.02,51.13 103.25,51.36 103.25,59.98 v1(103.97,60.71)
SDMMC1_D1: length 99.5
  TOP w0.173: v1(77.17,53.81) 76.6,53.24 73.49,53.24 72.85,52.6 72.85,32.21 72.41,31.76 54.14,31.76 53.29,30.91 J3.168 ; U16.19 103.87,59.6 v1(103.97,59.71)
  ART03 w0.16: v1(103.97,59.71) 104.36,59.32 104.36,51.65 103.35,50.65 75.49,50.65 75.01,51.13 75.01,53.7 75.6,54.29 76.68,54.29 v1(77.17,53.81)
SDMMC1_D2: length 99.8
  TOP w0.173: J3.169 54.19,30.9 54.53,31.25 72.93,31.25 73.41,31.72 73.41,52.38 73.75,52.72 76.14,52.72 v1(76.17,52.7) ; U16.14 v1(103.97,64.11)
  ART03 w0.16: v1(103.97,64.11) 102.61,64.11 101.27,62.76 101.27,56.62 100.89,56.23 96.58,56.23 96.4,56.42 96.4,57.09 96.21,57.28 95.94,57.28 95.76,57.09 95.76,56.42 95.57,56.23 95.3,56.23 95.12,56.42 95.12,57.09 94.93,57.28 92.88,57.28 92.7,57.09 92.7,56.04 92.51,55.85 92.24,55.85 92.06,56.04 92.06,57.09 91.87,57.28 91.6,57.28 91.42,57.09 91.42,56.04 91.23,55.85 90.96,55.85 90.78,56.04 90.78,57.09 90.59,57.28 90.3,57.28 89.94,56.92 89.94,53.54 89.64,53.24 76.7,53.24 v1(76.17,52.7)
SDMMC1_D3: length 99.2
  TOP w0.173: U16.15 104.07,63.21 v1(104.97,64.11) ; J3.170 55.09,30.38 55.43,30.73 73.5,30.73 73.97,31.2 73.97,51.72 74.41,52.16 76.62,52.16 v1(77.17,52.7)
  ART03 w0.16: v1(77.17,52.7) 90.14,52.7 90.58,53.14 90.58,55.02 90.83,55.27 91.48,55.27 91.66,55.08 91.66,54.11 91.85,53.92 92.12,53.92 92.3,54.11 92.3,55.08 92.49,55.27 92.76,55.27 92.95,55.08 92.95,54.11 93.13,53.92 93.4,53.92 93.59,54.11 93.59,55.08 93.77,55.27 94.04,55.27 94.23,55.08 94.23,54.11 94.41,53.92 94.68,53.92 94.87,54.11 94.87,55.08 95.05,55.27 95.5,55.27 95.91,55.68 101.42,55.68 101.75,56 101.75,62.53 102.77,63.55 104.42,63.55 v1(104.97,64.11)
SPK_CTRL: length 123.1
  TOP w0.173: J3.198 v1(80.29,22.71)
  ART03 w0.16: v1(33.53,39.99) 32.5,41.02 v1(29.51,41.02) 29.36,40.87 22.68,40.87 22.33,40.51 22.33,37.81 22.01,37.49 15.54,37.49 14.5,36.45 11.1,36.45 9.8,35.15 9.8,32.1 v1(10.36,31.55)
  BOTTOM w0.173: R25.1 10.55,31.74 v1(10.36,31.55) ; v1(80.29,22.71) 80.29,33.36 79.94,33.7 46.19,33.7 45.82,34.08 45.82,39.33 45.48,39.67 39.07,39.67 38.3,38.91 34.61,38.91 v1(33.53,39.99) ; R39.1 19.83,53.33 20.18,52.99 20.18,51.22 20.68,50.72 20.68,48.54 21.08,48.13 30.77,48.13 31.11,47.79 31.11,41.37 30.77,41.02 v1(29.51,41.02)
SPK_LN: length 32.8
  TOP w0.381: J8.2 v1(10.36,30.55) ; v1(13.72,40.33) C38.1 14.69,39.61 L6.2
  ART04 w0.381: v1(13.72,40.33) 14.45,40.33 14.83,40.72 14.83,44.09 14.12,44.8 8.64,44.8 8.26,44.42 8.26,30.17 8.64,29.79 9.98,29.79 10.36,30.17 v1(10.36,30.55)
SPK_LP: length 37.7
  TOP w0.381: J8.1 10.31,28.55 v1(10.36,28.5) ; v1(12.7,40.33) C37.1 11.73,39.61 L7.2
  ART04 w0.381: v1(12.7,40.33) 13.31,39.72 14.66,39.72 15.37,40.44 15.37,44.32 14.35,45.34 8.38,45.34 7.72,44.68 7.72,29.95 8.41,29.26 9.95,29.26 10.36,28.85 v1(10.36,28.5)
SPK_RN: length 16.5
  TOP w0.381: J8.3 v1(10.36,32.55) ; L8.2 11.73,42.04 C49.1 v1(12.7,41.33)
  ART04 w0.381: v1(12.7,41.33) 12.58,41.45 10.11,41.45 9.73,41.07 9.73,36.07 10.97,34.82 10.97,33.16 v1(10.36,32.55)
SPK_RP: length 16.5
  TOP w0.381: L9.2 14.69,42.04 C48.1 v1(13.72,41.33) ; J8.4 v1(10.36,34.55)
  ART04 w0.381: v1(10.36,34.55) 9.19,35.71 9.19,41.45 9.75,42.01 13.04,42.01 v1(13.72,41.33)
SPKN_OUT: length 66.6
  TOP w0.254: J3.16 v1(82.86,36.9)
  ART03 w0.254: v1(88.65,77.76) 88.32,77.43 88.32,76.12 87.72,75.52 84.83,75.52 84.02,74.72 84.02,71.31 83.54,70.82 73.65,70.82 73.07,70.24 73.07,37.12 73.58,36.61 82.57,36.61 v1(82.86,36.9)
  BOTTOM w0.254: R42.1 v1(88.65,77.76)
SPKP_OUT: length 67.4
  TOP w0.254: J3.15 82.96,36 v1(82.86,35.9)
  ART03 w0.254: v1(87.63,77.76) 87.91,77.48 87.91,76.28 87.55,75.93 84.66,75.93 83.62,74.89 83.62,71.48 83.36,71.23 73.42,71.23 72.66,70.48 72.66,36.94 73.4,36.2 82.56,36.2 v1(82.86,35.9)
  BOTTOM w0.254: R41.1 v1(87.63,77.76)
SYS_LED: length 131.6
  TOP w0.173: J3.28 83.14,47.7 82.83,47.4 v1(82.83,45.9) ; LED2.1 v1(5.75,85.4)
  ART03 w0.16: v1(5.75,85.4) 6.49,84.66 8.43,84.66 8.75,84.34 8.75,79.81 9.06,79.5 17.82,79.5 18.14,79.18 18.14,71.59 18.46,71.27 36.58,71.27 38.23,69.62 47.5,69.62 47.82,69.3 47.82,59.26 49.79,57.29 49.79,40.5 50.11,40.18 52.9,40.18 v1(53.39,40.67)
  BOTTOM w0.173: v1(53.39,40.67) 53.58,40.49 84.44,40.49 84.79,40.83 84.79,45.49 84.38,45.9 v1(82.83,45.9)
UART0_RX: length 2
  TOP w0.173: U12.2 2.93,77.83 R70.2
UART0_RX_M0_DEBUG: length 110.1
  TOP w0.173: v1(81.74,68.25) 81.53,68.25 81.19,68.59 J3.52 ; U12.4 v1(2.28,73.75)
  ART03 w0.16: v1(2.28,73.75) 2.28,74.74 2.62,75.08 5.82,75.08 6.48,74.42 17.18,74.42 17.5,74.1 17.5,70.97 17.89,70.58 35.97,70.58 37.73,68.83 46.66,68.83 46.95,68.53 46.95,58.22 v1(49.25,55.92)
  BOTTOM w0.173: v1(81.74,68.25) 81.74,61.16 80.41,59.84 80.41,56.66 80.01,56.26 49.59,56.26 v1(49.25,55.92)
UART0_TX: length 5
  TOP w0.173: U11.4 6.47,75.48 6.27,75.67 5.97,75.67 5.54,76.11 5.54,78 5.88,78.34 R69.2
UART0_TX_M0_DEBUG: length 107.5
  TOP w0.173: v1(82.74,68.25) 82.45,68.25 82.09,68.61 J3.51 ; U11.2 v1(7.12,77.6)
  ART03 w0.16: v1(7.12,77.6) 7.12,75.25 7.44,74.93 17.5,74.93 17.82,74.61 17.82,71.25 18.19,70.89 36.3,70.89 37.97,69.21 47.08,69.21 47.4,68.89 47.4,58.78 v1(49.25,56.92)
  BOTTOM w0.173: v1(49.25,56.92) 78.97,56.92 79.31,57.27 79.31,60.03 80.24,60.96 80.24,68.68 80.44,68.88 82.1,68.88 v1(82.74,68.25)
UART1_CTSN_M0: length 99.1
  TOP w0.173: J3.191 73.99,24.93 74.33,25.27 79.47,25.27 79.82,25.62 v1(79.82,57.48) ; R150.1 v1(119.7,63.12)
  ART03 w0.16: v1(79.82,57.48) 79.26,58.04 78.59,58.04 78.33,58.29 78.33,59.48 78.87,60.02 78.87,65.08 79.19,65.4 91.85,65.4 92.96,66.52 94.72,66.52 95.66,67.46 108.29,67.46 108.61,67.14 108.61,65.44 108.93,65.12 117.7,65.12 118.22,65.64 119.82,65.64 120.14,65.32 120.14,63.56 v1(119.7,63.12)
UART1_RTSN_M0: length 94.7
  TOP w0.173: v1(78.82,57.48) 78.82,26.13 78.47,25.78 73.43,25.78 73.09,25.43 J3.190 ; R154.1 v1(118.7,66.17)
  ART03 w0.16: v1(78.82,57.48) 78.33,57.48 77.95,57.86 77.95,65.62 78.27,65.94 91.74,65.94 92.7,66.89 94.32,66.89 95.25,67.82 108.77,67.82 109.09,67.5 109.09,65.9 109.41,65.58 117.4,65.58 117.96,66.14 118.67,66.14 v1(118.7,66.17)
UART1_RX_M0: length 92.4
  TOP w0.173: J3.189 72.19,25.94 72.53,26.29 77.89,26.29 78.23,26.63 78.23,57.74 78.58,58.09 79.3,58.09 v1(79.82,58.61) ; R152.1 v1(118.7,64.13)
  ART03 w0.16: v1(118.7,64.13) 118.62,64.21 108.08,64.21 107.67,64.62 107.67,66.46 107.35,66.78 96.49,66.78 95.38,65.66 93.47,65.66 92.38,64.57 80.14,64.57 79.82,64.25 v1(79.82,58.61)
UART1_TX_M0: length 93.8
  TOP w0.173: R153.1 v1(118.7,65.15) ; J3.188 71.29,26.45 71.63,26.8 77.4,26.8 77.75,27.14 77.75,58.26 78.09,58.61 v1(78.82,58.61)
  ART03 w0.16: v1(118.7,65.15) 118.24,64.69 108.46,64.69 108.23,64.92 108.23,66.79 107.91,67.11 96.06,67.11 95.03,66.07 93.12,66.07 92.05,65 79.72,65 79.4,64.68 79.4,59.19 v1(78.82,58.61)
UART2_RX_M1: length 14.3
  TOP w0.173: U23.12 95.66,42.92 95.41,43.18 92.78,43.18 D64.1 91.04,44.91 R116.1 88.56,46.8 J3.27
UART2_TX_M1: length 16.8
  TOP w0.173: J3.26 v1(85.45,45.9) ; U23.11 96.92,43.03 96.34,43.61 94.89,43.61 D65.1 93.58,44.91 R118.1 v1(92.99,44.14)
  BOTTOM w0.173: v1(92.99,44.14) 92.99,44.83 92.63,45.19 89.66,45.19 88.95,45.9 v1(85.45,45.9)
UART3_RX_M1: length 72.5
  TOP w0.173: J3.65 69.49,68.4 v1(69.35,68.27) ; v1(98.19,44.14) R113.1 98.79,44.91 D62.1 U23.9
  ART03 w0.16: v1(69.35,68.27) 69.35,68.27 69.01,68.6 64.8,68.6 62.81,66.62 62.81,46.93 63.13,46.61 v1(65.47,46.61)
  BOTTOM w0.173: v1(98.19,44.14) 97.61,43.56 95.29,43.56 94.95,43.91 94.95,46.83 94.51,47.27 67.08,47.27 66.43,46.61 v1(65.47,46.61)
UART3_TX_M1: length 69.7
  TOP w0.173: J3.66 68.59,67.5 v1(68.35,67.27) ; U23.10 98.2,42.96 D63.1 96.25,44.91 R114.1 v1(95.55,44.14)
  ART03 w0.16: v1(66.47,47.61) 65.97,47.12 63.65,47.12 63.22,47.55 63.22,66.47 64.88,68.13 67.53,68.13 67.77,67.89 68.35,67.31 v1(68.35,67.27)
  BOTTOM w0.173: v1(95.55,44.14) 96.09,44.68 96.09,47.32 95.68,47.73 66.58,47.73 v1(66.47,47.61)
UART4_RX_M0: length 81.1
  TOP w0.173: v1(67.35,67.27) 67.69,67.6 J3.67 ; U25.12 109.3,42.92 109.04,43.18 106.57,43.18 D71.1 104.84,44.91 R126.1 v1(103.47,44.91)
  ART03 w0.16: v1(65.47,47.61) 64.05,47.61 63.63,48.04 63.63,66.32 65.13,67.82 66.83,67.82 67.35,67.29 v1(67.35,67.27)
  BOTTOM w0.173: v1(65.47,47.61) 65.17,47.61 64.82,47.27 64.82,46.07 65.07,45.82 66.88,45.82 67.18,46.13 67.18,46.61 67.36,46.79 89.43,46.79 90.09,46.13 93.07,46.13 94.31,44.88 94.31,43.07 94.66,42.73 101.08,42.73 101.37,43.03 101.37,44.6 101.69,44.91 v1(103.47,44.91)
